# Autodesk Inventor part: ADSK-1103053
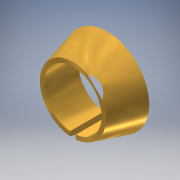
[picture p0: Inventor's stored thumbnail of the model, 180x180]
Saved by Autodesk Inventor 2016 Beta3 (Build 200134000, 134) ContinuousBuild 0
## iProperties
Shininess: 50.0
Length Units: 11272
Angle Units: 11279
Time Units: 11290
Mass Units: 11286
Length Display Precision: 4
Angle Display Precision: 2
Compacted: True
Created: 2000-08
Part Number: ADSK-1103053
Document SubType Name: Modeling
Description: TAPER NUT
Mass: 1.42288 g
Surface Area: 3.58073 cm^2
Volume: 0.16799 cm^3
Density: 8.47 g/cm^3
Material: Brass, Soft Yellow
Appearance: Brass - Satin
Density: 0.0
Volumn: 0.0
Area: 0.0
PropertySet Name: Model Information
Control State: 0
Master: False
Checked Out: False
Author: Autodesk, Inc.
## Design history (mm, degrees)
node "Extrusion1" dims "d1" = 4.7625, "d2" = -15 deg
  sketch "Sketch3"
    geometry: C1 r 5.874 at (0, 0)
    constraints: 1 centre point
    dimensions: "d0" = 11.7475 diameter of C1
node "Extrusion2" dims "d4" = 6.35, "d5" = 0
  sketch "Sketch4"
    geometry: C1 r 5.874 at (0, 0) reference; C2 r 4 at (0, 0)
    constraints: 1 centre point, 1 coincident
    dimensions: "d3" = 8 diameter of C2
node "Extrusion3" dims "d8" = 6.35, "d9" = 0
  sketch "Sketch5"
    geometry: L1 (0.406, 0)-(-0.406, 0); L2 (-0.406, 0)-(-0.406, -5.874); L3 (-0.406, -5.874)-(0.406, -5.874); L4 (0.406, -5.874)-(0.406, 0); C1 r 4 at (0, 0) reference; C2 r 5.874 at (0, 0) reference
    constraints: 8 end point, 2 parallel, 1 horizontal, 1 midpoint, 1 perpendicular, 1 tangent
    dimensions: "d6" = 0.8128 distance of L2.end L3.end; "d7" = 0.4064 distance from line of C1.centre L4 (= 0.5 x d6)
body "Solid1"
